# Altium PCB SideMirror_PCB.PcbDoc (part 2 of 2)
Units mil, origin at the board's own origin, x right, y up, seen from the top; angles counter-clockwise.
Board outline 2391.73 x 2364.18 mil, 2 copper layers (Top Layer, Bottom Layer), stack 62 mil thick; 77 components, 73 nets, 281 pads, 345 vias.
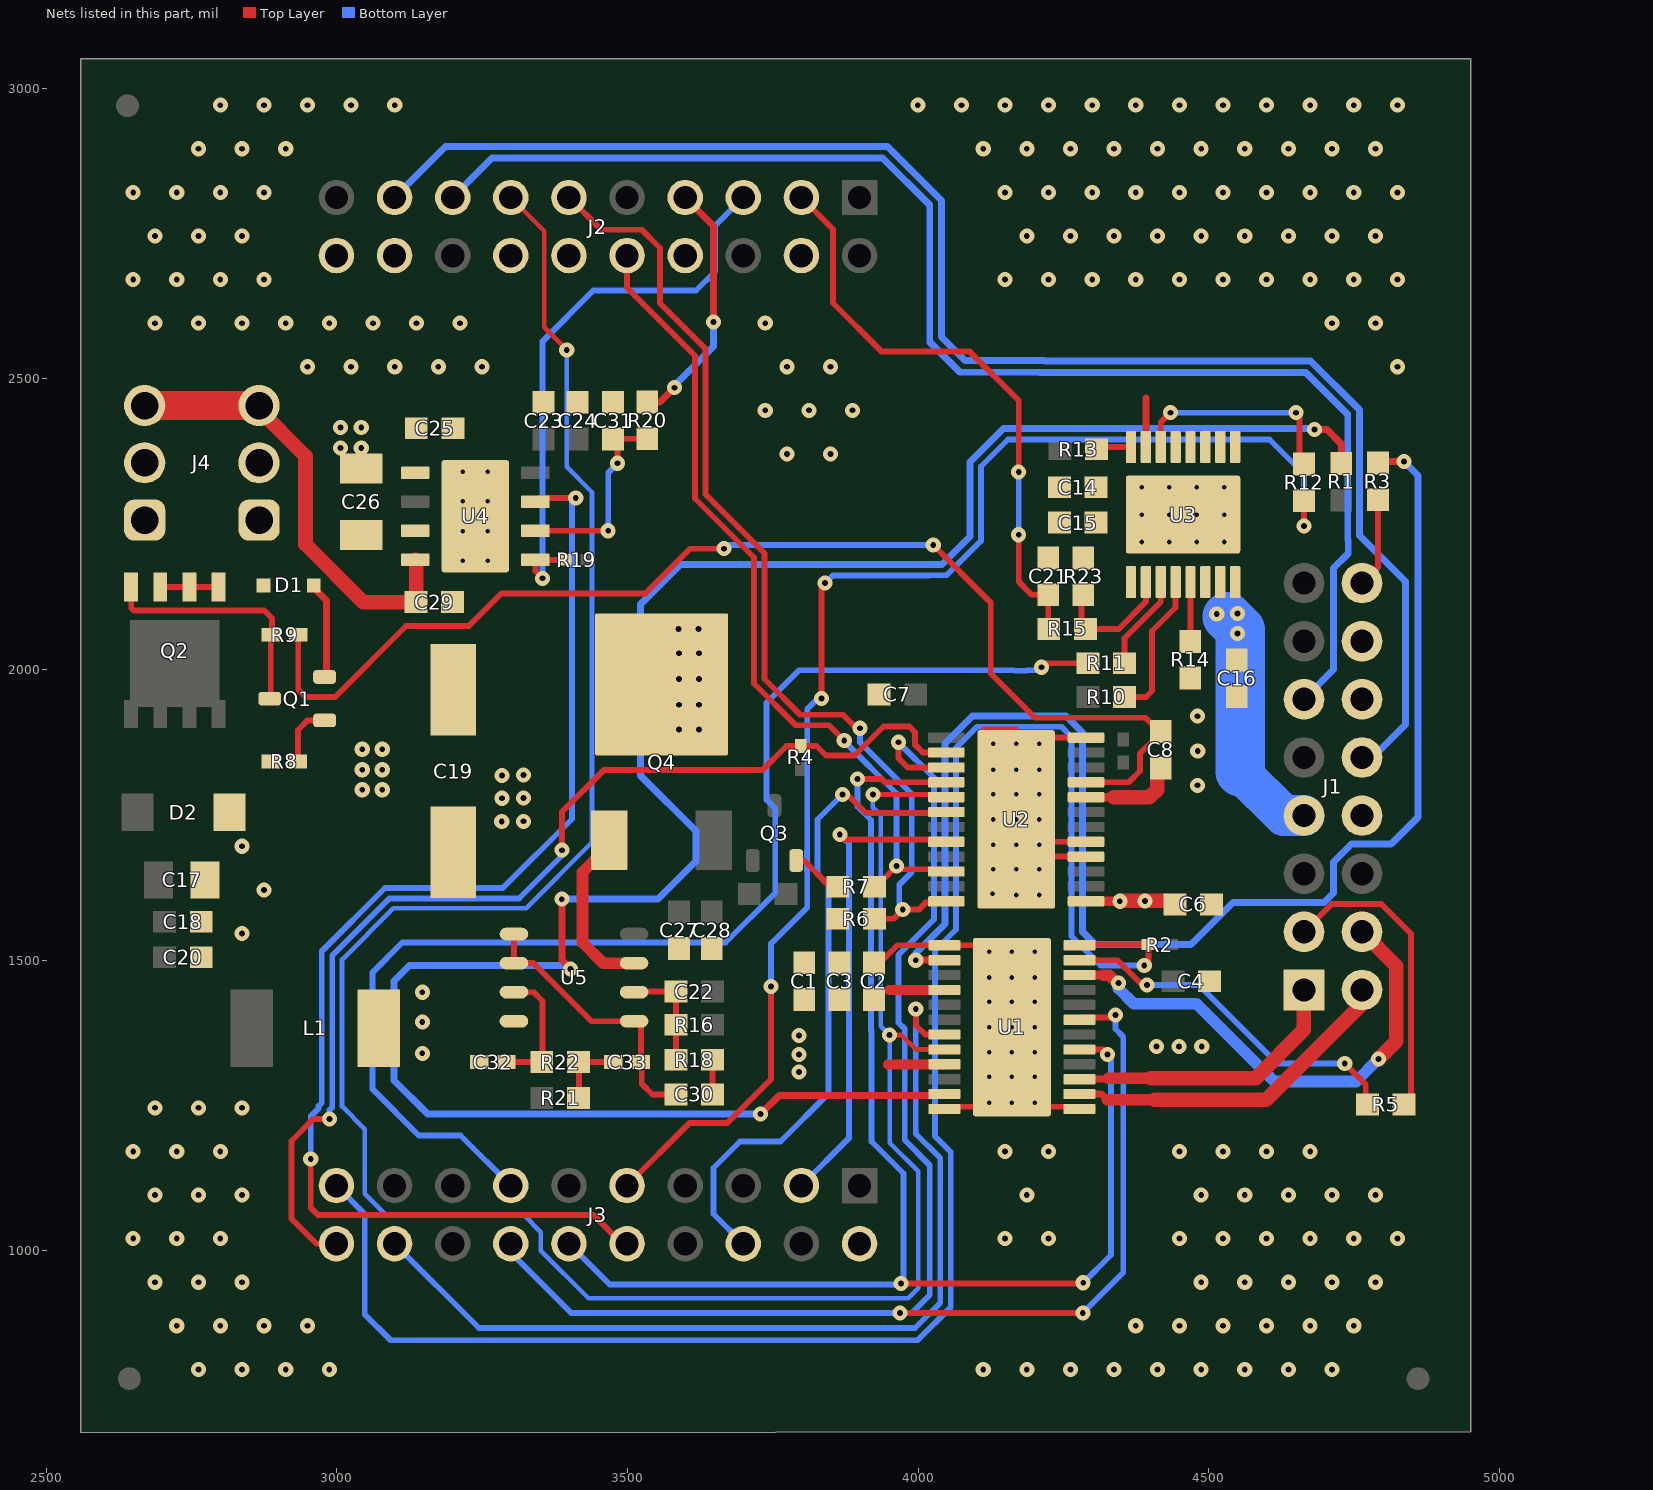
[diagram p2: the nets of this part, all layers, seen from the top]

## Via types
v1: diameter 26, hole 10, Top Layer to Bottom Layer, tented top, 270 vias
v2: diameter 19.68, hole 7.87, Top Layer to Bottom Layer, 46 vias
v3: diameter 19.68, hole 7.87, Top Layer to Bottom Layer, tented both sides, 28 vias
v4: diameter 28, hole 12, Top Layer to Bottom Layer, 1 vias

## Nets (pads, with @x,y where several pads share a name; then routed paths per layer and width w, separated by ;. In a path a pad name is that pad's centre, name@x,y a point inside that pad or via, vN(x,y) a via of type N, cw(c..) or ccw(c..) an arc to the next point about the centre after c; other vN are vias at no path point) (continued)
GND: C1.2 C2.2 C3.1 C4.2 C6.1 C7.2 C14.2 C15.2 C16.2 C17.2 C18.2 C19.2 C20.2 C21.1 C23.1 C24.1 C25.1 C26.2 C27.2 C28.2 C29.2 C31.1 C32.2 D2.2 J1.8 J1.12 J1.14 J2.4 J3.2 J4.2 Q3.2 R6.1 R7.1 R8.2 R23.1 U1.1 U1.13 U1.24 U1.25 U2.16 U2.17 U2.24 U2.25@4168.79,1742.13 U3.1 U3.9 U3.10 U3.11 U3.12 U3.13 U3.15 U4.3 U4.9@3238.19,2263.78 U5.4 | length 1580.5
  Top Layer w10: Q3.2@3790.19,1671.51 3803.61,1671.51 3848.85,1626.26 R7.1@3861.72,1626.26 ; C2.2@3924,1495.5 3934.41,1495.5 3964.5,1525.59 3985,1525.59 3985.28,1525.87 4006.72,1525.87 4007,1525.59 U1.13@4045.27,1525.59 4111.41,1525.59 4122.71,1514.29 4149.71,1514.29 4152,1512 4152,1455.71 4152,1394.26 v2(4161.42,1384.84) 4161.42,1361.22 U1.25@4161.42,1360.24 ; U1.24@4045.27,1244.09 4049.13,1247.95 4119.86,1247.95 4161.42,1289.51 4161.42,1313.98 U1.25@4161.42,1360.24 ; 4113.12,1897.13 4168.79,1897.13 v3(4168.79,1872.05) U2.25@4168.79,1831 ; U2.25@4208.16,1703.74 U2.17@4288.87,1703.74 ; U1.1@4277.56,1244.09 4273.7,1247.95 4206.05,1247.95 4203,1251 4203,1318.65 U1.25@4161.42,1360.24 ; U2.16@4288.87,1678.15 4232.77,1678.15 v2(4168.79,1742.13) v2(4168.79,1785.43) v2(4168.79,1827.56) U2.25@4168.79,1831 ; U2.24@4288.87,1882.87 4220.66,1882.87 U2.25@4168.79,1831
  Top Layer w12: U3.15@4391.82,2368.07 U3.15@4391.82,2382.83 4391.82,2467.24
  other v1: 2762,796 2837,796 2912,796 2987,796 4112,796 4187,796 4262,796 4337,796 4412,796 4487,796 4562,796 4637,796 4712,796 2724.5,871 2799.5,871 2874.5,871 2949.5,871 4374.5,871 4449.5,871 4524.5,871 4599.5,871 4674.5,871 4749.5,871 2687,946 2762,946 2837,946 4487,946 4562,946 4637,946 4712,946 4787,946 2649.5,1021 2724.5,1021 2799.5,1021 4149.5,1021 4224.5,1021 4449.5,1021 4524.5,1021 4599.5,1021 4674.5,1021 4749.5,1021 4824.5,1021 2687,1096 2762,1096 2837,1096 4187,1096 4487,1096 4562,1096 4637,1096 4712,1096 4787,1096 2649.5,1171 2724.5,1171 2799.5,1171 4149.5,1171 4224.5,1171 4449.5,1171 4524.5,1171 4599.5,1171 4674.5,1171 2687,1246 2762,1246 2837,1246 4410,1351.3 4449,1351.3 4488,1351.3 2837,1546 2874.5,1621 2837,1696 3283.7,1738.47 3321,1738.9 3284.13,1778.57 3321,1779 3284.13,1818 3321,1818.43 3774.5,2371 3849.5,2371 3737,2446 3812,2446 3887,2446 2949.5,2521 3024.5,2521 3099.5,2521 3174.5,2521 3249.5,2521 3774.5,2521 3849.5,2521 4824.5,2521 2687,2596 2762,2596 2837,2596 2912,2596 2987,2596 3062,2596 3137,2596 3212,2596 3737,2596 4712,2596 4787,2596 2649.5,2671 2724.5,2671 2799.5,2671 2874.5,2671 4149.5,2671 4224.5,2671 4299.5,2671 4374.5,2671 4449.5,2671 4524.5,2671 4599.5,2671 4674.5,2671 4749.5,2671 4824.5,2671 2687,2746 2762,2746 2837,2746 4187,2746 4262,2746 4337,2746 4412,2746 4487,2746 4562,2746 4637,2746 4712,2746 4787,2746 2649.5,2821 2724.5,2821 2799.5,2821 2874.5,2821 4149.5,2821 4224.5,2821 4299.5,2821 4374.5,2821 4449.5,2821 4524.5,2821 4599.5,2821 4674.5,2821 4749.5,2821 4824.5,2821 2762,2896 2837,2896 2912,2896 4112,2896 4187,2896 4262,2896 4337,2896 4412,2896 4487,2896 4562,2896 4637,2896 4712,2896 4787,2896 2799.5,2971 2874.5,2971 2949.5,2971 3024.5,2971 3099.5,2971 3999.5,2971 4074.5,2971 4149.5,2971 4224.5,2971 4299.5,2971 4374.5,2971 4449.5,2971 4524.5,2971 4599.5,2971 4674.5,2971 4749.5,2971 4824.5,2971
  other v2: 4122.05,1341.54 4161.42,1341.54 4200.79,1341.54 4122.05,1384.84 4200.79,1384.84 4122.05,1428.15 4161.42,1428.15 4200.79,1428.15 4129.42,1656.69 4168.79,1656.69 4208.16,1656.69 4129.42,1698.82 4168.79,1698.82 4208.16,1698.82 4129.42,1742.13 4208.16,1742.13 4129.42,1785.43 4208.16,1785.43 4129.42,1827.56 4208.16,1827.56 3216.54,2238.19 3259.84,2238.19 3216.54,2289.37 3259.84,2289.37
  other v3: 4122.05,1254.92 4161.42,1254.92 4200.79,1254.92 4122.05,1299.41 4161.42,1299.41 4200.79,1299.41 4122.05,1470.28 4161.42,1470.28 4200.79,1470.28 4122.05,1514.76 4161.42,1514.76 4200.79,1514.76 4168.79,1612.2 4208.16,1612.2 4128,1614 4129.42,1872.05 4208.16,1872.05 3216.54,2187.01 3259.84,2187.01 3216.54,2340.55 3259.84,2340.55
HALLX: J1.10 J2.17 | length 2702.8
  Bottom Layer w12: J2.17@3108,2812.2 J2.17@3099.21,2812.2 3186.88,2899.87 3947.23,2899.87 4039.87,2807.23 4039.87,2572.13 4080.58,2531.42 4216.75,2531.42 4217.3,2530.87 4675.14,2530.87 4759.04,2446.97 4759.04,2230.96 4838.59,2151.41 4838.59,1905.81 4781.6,1848.82 J1.10@4763.78,1848.82
HALLY: J1.11 J2.15 | length 2410.4
  Bottom Layer w12: J2.15@3199.21,2812.2 3267.01,2880 3939,2880 4020,2799 4020,2563.89 4072.34,2511.55 4208.52,2511.55 4209.07,2511 4666.9,2511 4739.17,2438.74 4739.17,2222.73 4740,2221.89 4740,2199.96 4714.91,2174.87 4714.91,1999.94 J1.11@4663.78,1948.82
HEATER: C16.1 J1.7 U3.6 U3.7 U3.8 | length 420
  Top Layer w12: U3.6@4491.32,2150.54 U3.6@4494.18,2150.54
  Bottom Layer w70: 4554,1824 4629.18,1748.82 J1.7@4663.78,1748.82
  Bottom Layer w85: 4531.65,2090.96 4554,2068.62 4554,1824
  other v1: 4549.69,2061.97 4513.79,2095.78 4549.69,2096.22
HEATERBTN: J2.20
IPROP1l: J2.10 R7.2 U2.10 | length 1402.4
  Top Layer w10: J2.10@3499.21,2712.2 3499.21,2656.79 3616.17,2539.83 3616.17,2294.42 3717.72,2192.87 3717.72,1976.24 3789.6,1904.37 3846.63,1904.37 v1(3873,1878) ; R7.2@3937.89,1639.44 3939.16,1638.16 v1(3963,1662) 3963,1659.32 3965.91,1656.42 4044.85,1656.42 U2.10@4048.71,1652.56
  Bottom Layer w10: v1(3873,1878) 3873,1876.72 3963,1786.72 v1(3963,1662)
IPROP2l: J2.11 R6.2 U2.12 | length 1708
  Top Layer w10: J2.11@3399.21,2812.2 3454.87,2756.54 3524.61,2756.54 3555.83,2725.33 3555.83,2630.14 3634.04,2551.92 3634.04,2301.83 3735.6,2200.27 3735.6,1983.65 3797,1922.24 3870.76,1922.24 3894,1899 v1(3900,1899) ; R6.2@3924.71,1571.26 3957.89,1571.26 v1(3973.63,1587) 4000.95,1587 4012.95,1599 4039.18,1599 4045.14,1604.95 U2.12@4048.71,1601.38
  Bottom Layer w10: v1(3900,1899) 3900,1875 3989.1,1785.9 3989.1,1651.5 3967.55,1629.96 3967.55,1593.07 v1(3973.63,1587)
L3: R5.1 U1.11 | length 624.8
  Top Layer w10: U1.11@4277.56,1500 4343.05,1500 v1@4389,1454.05 ; v1@4389.75,1453.31 v1@4389,1454.05 ; v1(4393.87,1457.13) 4392.07,1457.13 v1@4389,1454.05 ; v1(4734,1322.25) 4770,1286.25 4770,1262.5 4759.14,1251.64 R5.1@4760.25,1251.64
  Bottom Layer w10: v1(4393.87,1457.13) 4483.03,1457.13 4617.9,1322.25 v1(4734,1322.25)
LATCH: J3.13 R11.1 | length 2171.9
  Top Layer w10: v1(4212,2004) 4218.99,2010.99 R11.1@4292.06,2010.99
  Bottom Layer w10: J3.13@3299.21,1112.2 3212.87,1198.55 3141.05,1198.55 3061.5,1278.1 3061.5,1479.32 3112.42,1530.24 3668.79,1530.24 3754.25,1615.69 3754.25,1760.88 3739.25,1775.88 3739.25,1942.9 3795.12,1998.77 4165.06,1998.77 4165.74,1998.1 4187.18,1998.1 4187.85,1998.77 4206.77,1998.77 v1(4212,2004)
LBLSP: R1.1 U1.23 | length 3794
  Top Layer w12: v1(3387,1605) 3387,1500 v1(3402,1485) ; v1(3729,1235.3) 3760.53,1266.83 4042.42,1266.83 U1.23@4045.27,1269.68 ; v1(4681.98,2412.87) 4703.31,2412.87 4728,2388.18 R1.1@4728,2354.33
  Bottom Layer w12: v1(3387,1605) 3552.31,1605 3618,1670.69 3618,1722 3522,1818 3522,2112 3591,2181 4009.24,2181 4009.37,2181.13 4041.13,2181.13 4089.25,2229.25 4089.25,2282.32 4089.44,2282.51 4089.44,2357.18 4147.02,2414.75 4680.11,2414.75 v1(4681.98,2412.87) ; v1@3399.21,1482.21 v1(3402,1485) 3396,1491 3125.15,1491 3098.25,1464.1 3098.25,1293.33 3156.27,1235.3 v1(3729,1235.3)
LED: J2.18
LED3: J1.3 R5.2 | length 524.2
  Top Layer w10: J1.3@4663.78,1548.82 4711.65,1596.69 4796.92,1596.69 4848,1545.61 4848,1263.69 R5.2@4835.95,1251.64
LEFT: J2.12
LIN: C29.1 J4.3 U4.4 | length 1010.2
  Top Layer w25: J4.3@2852.65,2460.63 2859.15,2454.14 2862.65,2450.64 2946,2367.29 2946,2215.74 3045.6,2116.14 C29.1@3136.22,2116.14 3136.22,2187.4 U4.4@3134.84,2188.78
  Top Layer w50: J4.3@2669.3,2454.14 2859.15,2454.14 J4.3@2866.15,2454.14
  Bottom Layer w10: J4.3@2852.65,2460.63 2872.66,2460.63 J4.3@2872.66,2452.34
  Bottom Layer w50: J4.3@2669.3,2454.14 J4.3@2866.15,2454.14
LTURN: R3.1 U1.14 | length 2430.5
  Top Layer w12: v1(3996,1500) U1.14@4045.27,1500 ; R3.1@4791,2355.1 4793.9,2358 v1(4835.95,2358)
  Bottom Layer w12: v1(3996,1500) 3996,1512.31 4046.13,1562.43 4046.13,1873.13 4093.45,1920.45 4254.39,1920.45 4282.9,1891.94 4282.9,1548.92 4304.82,1527 4469.59,1527 4541.59,1599 4698,1599 4714.91,1615.91 4714.91,1669.06 4745.79,1699.94 4813.94,1699.94 4860,1746 4860,2333.95 v1(4835.95,2358)
NetC22_2: C22.2 R16.1 R18.2 U5.6 | length 189.8
  Top Layer w10: U5.6@3511.35,1445 3512.35,1446 C22.2@3583.5,1446 R16.1@3583.5,1389 R18.2@3583.5,1328.74
NetC30_1: C30.1 R18.1 | length 59.7
  Top Layer w10: C30.1@3646.5,1269 R18.1@3646.5,1328.74
NetC30_2: C30.2 C33.1 U5.1 U5.2 U5.5 | length 484.5
  Top Layer w10: U5.1@3304.65,1545 U5.2@3304.65,1495 3338,1495 3438,1395 U5.5@3511.35,1395 3523.03,1395 3523.03,1326.39 3524.62,1324.79 3524.62,1287.55 3543.17,1269 C30.2@3583.5,1269
NetC31_2: C31.2 R20.2 U4.6 | length 349.3
  Top Layer w10: U4.6@3341.54,2238.78 v1(3466.75,2238.78) ; v1(3483,2355) 3483,2389.24 C31.2@3475.24,2397 R20.2@3531.17,2397
  Bottom Layer w10: v1(3466.75,2238.78) 3466.75,2338.75 v1(3483,2355)
NetC32_1: C32.1 R22.2 U5.3 | length 220.2
  Top Layer w10: C32.1@3293.82,1324.79 3353.64,1324.79 3353.64,1429.98 3338.62,1445 U5.3@3304.65,1445
NetC33_2: C33.2 R21.2 R22.1 | length 122.5
  Top Layer w10: R21.2@3416.63,1263 3416.63,1324.79 C33.2@3477.38,1324.79
NetD1_2: D1.2 Q1.2 | length 169.7
  Top Layer w12: D1.2@2956.31,2145 2982.28,2119.02 2982.28,1990.71 Q1.2@2978.98,1987.4
NetQ1_1: Q1.1 R8.1 | length 106.6
  Top Layer w10: R8.1@2933.24,1842 2933.24,1896.06 2949.79,1912.6 Q1.1@2978.98,1912.6
NetQ1_3: Q1.3 Q2.4 R9.1 | length 425.8
  Top Layer w10: Q2.4@2646.1,2142.3 2646.1,2106.3 2650.71,2101.69 2874.93,2101.69 2888.62,2088 2888.62,2062.25 R9.1@2886.38,2060 2886.38,1951.89 Q1.3@2884.49,1950
NetQ4_1: Q4.1 U5.7 | length 302.7
  Top Layer w20: Q4.1@3478.15,1706.69 3422.63,1651.18 3422.63,1530.37 3458,1495 U5.7@3511.35,1495
NetR10_2: R10.2 U3.4 | length 255.6
  Top Layer w10: R10.2@4355.06,1953 4392,1953 4402.27,1963.27 4402.27,2066.27 4443,2107 U3.4@4443,2150.54
NetR11_2: R11.2 U3.3 | length 165.4
  Top Layer w10: R11.2@4355.05,2010.99 4355.05,2054.04 4417.41,2116.39 U3.3@4417.41,2150.54
NetR12_2: R12.2 U3.14 | length 382.2
  Top Layer w10: U3.14@4417.41,2382.83 4417.41,2425.41 v1(4434,2442) ; v1(4650,2442) 4656.11,2435.89 4656.11,2361.17 R12.2@4663.78,2353.5
  Bottom Layer w10: v1@4428.03,2442 v1(4434,2442) v1(4650,2442)
NetR13_2: R13.2 U3.16 | length 58.8
  Top Layer w10: R13.2@4309.53,2388 4314.7,2382.83 U3.16@4366.23,2382.83
NetR14_2: R14.2 U3.5 | length 125.1
  Top Layer w10: U3.5@4472.45,2150.54 U3.5@4468.59,2150.54 R14.2@4468.59,2049.63 ; R14.2@4468.59,2049.63 R14.2@4470.12,2048.1 ; R14.2@4468.59,2049.63 R14.2@4470.12,2048.1 ; R14.2@4470.12,2048.1 4470.12,2056.13 R14.2@4470.12,2048.1
NetR15_2: R15.2 R23.2 U3.2 | length 222.6
  Top Layer w10: R23.2@4286.07,2120.46 4281.03,2125.5 4281.03,2076.72 R15.2@4287.75,2070 4345.06,2070 4391.82,2116.76 U3.2@4391.82,2150.54
nFAULT_8873: J3.20 R4.1 U2.2 | length 1921.4
  Top Layer w10: v1(2987.1,1227) 2959.97,1227 2922,1189.03 2922,1055.21 2965,1012.2 J3.20@2999.21,1012.2 J3.20@2999.21,1026.79 ; v1(3387.5,1689.32) 3387.5,1755.5 3459,1827 3732,1827 3773.5,1868.5 R4.1@3798,1868.5 3825.04,1868.5 3841.42,1852.13 3890.44,1852.13 3940.31,1902 3984.77,1902 3994.87,1891.9 3994.87,1870.46 4008.05,1857.28 U2.2@4048.71,1857.28 U2.2@4044.85,1861.14
  Bottom Layer w10: v1(2987.1,1227) 2987.1,1242.21 2992,1247.11 2992,1508.11 3090.14,1606.24 3313.47,1606.24 3387.5,1680.28 v1(3387.5,1689.32)
nFAULT_8906: J3.19 R2.1 U1.12 | length 3148.9
  Top Layer w10: U1.12@4277.56,1525.59 4278.97,1527 R2.1@4396.31,1527 4396.31,1498.31 v1(4389,1491)
  Bottom Layer w10: J3.19@2999.21,1112.2 3048,1063.42 3048,890.53 3092.53,846 3999,846 4056,903 4056,1170 4029,1197 4029,1516.84 4065,1552.84 4065,1865.31 4101.26,1901.57 4246.58,1901.57 4264.03,1884.12 4264.03,1541.1 4314.06,1491.06 4314,1491 v1(4389,1491)
nRST: J3.10 U4.7 | length 2170.5
  Top Layer w10: v1(2955,1158) 2955,1074 2967.17,1061.83 3440.95,1061.83 3490.58,1012.2 J3.10@3499.21,1012.2 ; U4.7@3341.54,2288.78 3347.76,2295 v1(3411,2295)
  Bottom Layer w10: v1(2955,1158) 2955,1231.49 2968.6,1245.09 2968.6,1248.99 2974.13,1254.52 2974.13,1515.51 3082.74,1624.12 3285.42,1624.12 3404.36,1743.06 3404.36,2288.36 v1(3411,2295)
nSCS_8873: J3.6 U2.6 | length 1149.1
  Top Layer w10: v1@3874.12,1789.12 3870,1793.24 v1(3870,1785) 3878.24,1785 3910.12,1753.13 4046.91,1753.13 U2.6@4048.71,1754.92
  Bottom Layer w10: J3.6@3699.21,1012.2 3648,1063.42 3648,1142.55 3693.45,1188 3763.22,1188 3845.59,1270.38 3845.59,1629.52 3827,1648.11 3827,1660.04 3826.89,1660.16 3826.89,1681.59 3827,1681.71 3827,1742 v1(3870,1785)
nSCS_8906: J3.18 U1.19 | length 1629.4
  Top Layer w10: v1(3996,1416) 3996,1388.25 3997.34,1386.91 4012.2,1372.05 U1.19@4045.27,1372.05
  Bottom Layer w10: J3.18@3099.21,1012.2 3244.42,867 3994.72,867 4038,910.28 4038,1159.52 3997.34,1200.17 3996,1201.52 v1(3996,1416) 3990.42,1416 v1@3990.37,1415.94
PH_8873: J3.3 U2.8 | length 833
  Top Layer w10: v1(3865.32,1716.09) 3873.81,1707.6 4044.85,1707.6 U2.8@4048.71,1703.74
  Bottom Layer w10: J3.3@3799.21,1112.2 3881.34,1194.33 3881.34,1700.06 v1(3865.32,1716.09)
RIGHT: J2.14
RXD: J2.5 R19.1 U4.5 | length 995.1
  Top Layer w10: v1@3359.64,2157 v1(3354,2157) 3341.54,2169.46 U4.5@3341.54,2188.78 3391.42,2188.78 R19.1@3391.93,2189.29
  Bottom Layer w10: v1(3354,2157) 3354,2565 3441,2652 3618,2652 3651,2685 3651,2763.99 J2.5@3699.21,2812.2
SCLK: J2.13 U1.20 U2.5 | length 4270.3
  Top Layer w8: J2.13@3299.21,2812.2 3356.83,2754.59 3356.83,2588.7 v1(3395.53,2550) ; v1(3922.16,1785) 4034.8,1785 4037.8,1782 4040.8,1785 4046.8,1779 4047,1779.2 4047.2,1779 U2.5@4048.71,1780.51 ; v1(3951,1371.27) 3970.99,1371.27 3995.81,1346.46 U1.20@4045.27,1346.46
  Bottom Layer w8: v1(3395.53,2550) 3395.53,2348.68 3438.97,2305.24 3438.97,1702.76 3325.58,1589.37 3097.13,1589.37 3008.88,1501.12 3008.88,1248.37 3048,1209.25 3048,1098.16 3084.33,1061.83 3321.17,1061.83 3351,1032 3351,1000.48 3432.85,918.63 3982.83,918.63 3999.95,935.75 3999.95,1136.55 3951,1185.5 v1(3951,1371.27) 3936,1386.27 3936,1749 3922.16,1762.84 v1(3922.16,1785)
SDI: J3.12 U1.5 U2.4 | length 2453
  Top Layer w10: v1(3895.92,1812) 3936.87,1812 3942.77,1806.1 U2.4@4048.71,1806.1 ; v1@3972,942 v1(3970.5,943.5) v1@3973.35,943.5 ; v1@3972,948.15 3975,945.15 v1@3973.35,943.5 ; U1.5@4277.56,1346.46 4317.53,1346.46 v1(4326,1337.99) ; v1(4284,945) 4282.5,943.5 v1@3973.35,943.5
  Bottom Layer w10: J3.12@3399.21,1012.2 3469.42,942 3975,942 3975,1132.87 3919.71,1188.16 3919.71,1378.7 3919.13,1379.28 3919.13,1741.38 3895.92,1764.59 v1(3895.92,1812) ; v1(4284,945) 4332,993 4332,1331.99 v1(4326,1337.99)
SDO: J3.14 U1.7 U2.3 | length 2863.4
  Top Layer w10: v1(3969,893) v1(4283.39,893) ; v1@3969,1878 v1(3966,1875) 3966,1848 3982.31,1831.69 U2.3@4048.71,1831.69 ; U1.7@4277.56,1397.64 4281.42,1401.5 4335.16,1401.5 v1(4339.41,1405.75)
  Bottom Layer w10: J3.14@3299.21,1012.2 3299.21,997.16 3403.37,893 v1(3969,893) 3989.1,893 4020,923.91 4020,1147.39 3976.87,1190.51 3976.87,1381.99 3966,1392.87 3966,1509 3995.4,1538.4 4027.25,1570.25 4027.25,1813.75 v1(3966,1875) ; v1(4283.39,893) 4352.91,962.52 4352.91,1368.09 4339.41,1381.59 v1(4339.41,1405.75)
SEL1: J3.9 R12.1 | length 2386.3
  Top Layer w10: J3.9@3499.21,1112.2 3607.17,1220.16 3671.9,1220.16 3747,1295.26 v1(3747,1455) ; v1(3834,1950) 3834,2142.82 v1(3840,2148.82) ; v1(4663.78,2247) R12.1@4663.78,2290.5
  Bottom Layer w10: v1(3747,1455) 3747,1528.47 3809.13,1590.6 3809.13,1652.64 3809.01,1652.75 3809.01,1689 3809.13,1689.11 3809.13,1932.23 3832.9,1956 3834,1954.9 v1(3834,1950) ; v1(3840,2148.82) 3853.05,2161.87 4018.87,2161.87 4019.25,2162.25 4048.94,2162.25 4108.13,2221.43 4108.13,2274.5 4108.32,2274.69 4108.32,2349.36 4154.83,2395.87 4604.44,2395.87 4663.78,2336.53 v1(4663.78,2247)
SNS: C21.2 J2.3 R15.1 | length 1026.6
  Top Layer w10: J2.3@3799.21,2812.2 3853.7,2757.72 3853.7,2630.8 3937.5,2547 4089,2547 4173,2463 v1(4173,2340) ; v1(4173,2232) 4173,2151 4195.25,2128.75 C21.2@4224.03,2128.75 4224.03,2070.73 R15.1@4224.76,2070
  Bottom Layer w10: v1(4173,2232) 4173,2334 4170,2337 v1(4173,2340)
TURN: J1.16 R3.2 | length 154.6
  Top Layer w10: J1.16@4763.78,2148.82 4791,2176.04 R3.2@4791,2292.11
TXD: J2.7 R20.1 | length 437.7
  Top Layer w12: R20.1@3531.17,2459.99 3555.94,2459.99 v1(3580.95,2485) ; J2.7@3599.21,2812.2 3648,2763.42 v1(3648,2598)
  Bottom Layer w12: v1@3576.55,2484.45 3648,2555.89 v1(3648,2598)
UP: J2.8
Vbat: D1.1 J4.1 Q2.1 Q2.2 Q2.3 | length 102.3
  Top Layer w10: Q2.3@2694.49,2143.91 Q2.3@2696.1,2142.3 Q2.2@2746.1,2142.3 Q2.1@2796.1,2142.3
VCP: C8.2 R9.2 U2.21 | length 2073.8
  Top Layer w10: R9.2@2931.73,2064.29 R9.2@2932.8,2063.23 ; R9.2@2933.62,2060 2933.62,1965.38 2946,1953 2997,1953 3119,2075 3227,2075 3283.13,2131.13 3530.83,2131.13 3607.7,2208 v1(3666,2208) ; v1(4026,2214.36) 4118.29,2122.07 4125,2115.33 4125,1993.23 4201.23,1917 4391.26,1917 4410,1898.26 4410,1884 4381.88,1855.88 4381.88,1825.45 4362.53,1806.1 U2.21@4288.87,1806.1
  Bottom Layer w10: v1(3666,2208) 3672.36,2214.36 v1(4026,2214.36)
Vsup: C1.1 C2.1 C3.2 C6.2 C8.1 C14.1 C15.1 C19.1 C25.2 C26.1 L1.2 Q4.4 R14.1 U1.16 U1.21 U2.13 U2.20 U3.17@4455.8,2266.69 U4.1 | length 685.3
  Top Layer w10: L1.2@3066.57,1358.27 L1.2@3066.57,1393.35
  Top Layer w12: U2.13@4288.87,1599.83 U2.13@4288.87,1601.38 ; R14.1@4468.03,1983.7 R14.1@4468.03,1985.5
  Top Layer w15: U2.20@4288.87,1780.51 4336.5,1780.51
  Top Layer w17: 3947.69,1320.87 U1.21@4045.27,1320.87 ; 3949.73,1448.82 U1.16@4045.27,1448.82 ; U2.13@4317,1601.38 v1(4347,1601.38)
  Top Layer w25: Q4.4@3475.04,1974.41 Q4.4@3558.63,1974.41 Q4.4@3567.91,1974.41 ; 4336.5,1780.51 4398,1780.51 4411.1,1793.61 4411.1,1810.27 ; v1(4347,1601.38) 4347.62,1602 v1(4390.14,1602) 4429.51,1602 C6.2@4430.12,1601.38 ; U3.17@4404.2,2318.28 U3.17@4455.8,2266.69 ; C6.2@4441.5,1590 C6.2@4430.12,1601.38 ; C6.2@4441.69,1596 4436.31,1601.38 C6.2@4430.12,1601.38
  other v1: 3794.87,1307.48 3795,1338 3147,1339.79 3794.87,1370.3 3147,1393.79 3147,1444.79 3043.62,1793.24 3078.11,1793.24 4480.71,1800.85 3043.62,1827.56 3078.11,1827.56 4481.07,1860 3043.62,1863 3078,1863 3588.61,1897.13 3623.1,1897.13 4480.71,1919.85 3588.61,1939.63 3623.1,1939.63 3588.72,1983.65 3623.1,1983.65 3588.61,2028 3623.1,2028 3587.79,2070 3622.17,2070 3006,2381.3 3042,2381.3 3006,2416.58 3042,2416.58
  other v2: 4432.17,2219.44 4479.42,2219.44 4432.17,2266.69 4479.42,2266.69 4432.17,2313.93 4479.42,2313.93
  other v3: 4384.93,2219.44 4526.66,2219.44 4384.93,2266.69 4526.66,2266.69 4384.93,2313.93 4526.66,2313.93
X1: J1.1 U1.3 | length 497.9
  Top Layer w12: U1.3@4277.56,1295.28 4323.38,1295.27
  Top Layer w20: 4327.26,1297.06 4400.6,1297.06
  Top Layer w25: 4400.6,1297.06 4580.67,1297.06 4663.78,1380.17 J1.1@4663.78,1448.82 J1.1@4654.96,1440
X2/Y1: J1.4 U1.10 | length 867.8
  Top Layer w15: U1.10@4277.56,1474.41 4318.42,1474.41
  Top Layer w20: 4318.42,1474.41 4328.88,1474.41 4342.28,1461 v1(4344.72,1461)
  Top Layer w25: J1.4@4763.78,1548.82 4822.63,1489.97 4822.63,1360.63 v1(4791.93,1329.93)
  Bottom Layer w20: v1(4344.72,1461) 4344.72,1451.37 4371.1,1425 4479,1425 4612.62,1291.38 4753.38,1291.38 v1(4791.93,1329.93)
Y2: J1.2 U1.2 | length 582.5
  Top Layer w12: U1.2@4277.56,1269.68 4315.75,1269.68 4325.43,1260
  Top Layer w20: 4325.43,1260 4407,1260
  Top Layer w25: 4407,1260 4599,1260 4763.78,1424.78 J1.2@4763.78,1448.82
pads on no net: FID1.1 FID2.1 FID3.1 J1.9 J2.19 J3.8 J3.16 U1.4 U1.9 U1.15 U1.17 U1.18 U1.22 U2.25@4168.79,1742.13 U3.17@4455.8,2266.69 U4.9@3238.19,2263.78

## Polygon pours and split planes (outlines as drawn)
Vbat on Top Layer "TOP_LAYER_VBAT_P038" (solid, remove dead copper, pour order 38): 2905,2298.48 2905,2127.75 2674.64,2127.75 2592.49,2209.9 2592.49,2278.79 2612.17,2298.48
no net on Top Layer "TOP_LAYER_NONET_P040" (solid, remove dead copper, pour order 40): 2779.42,1549.85
12V on Top Layer "TOP_LAYER_12V_P036" (solid, remove dead copper, pour order 36): 2889,1317 2889,1449 2732.87,1449 2732.95,2085 2559.05,2085 2559.06,1441.19 2559.05,1317
no net on Top Layer "TOP_LAYER_NONET_P046" (solid, remove dead copper, pour order 46): 3257.87,1896.97
Vsup on Top Layer "TOP_LAYER_VSUP_P008" (solid, remove dead copper, pour order 8): 2978.98,1296 3161.33,1296 3194.57,1335.86 3194.57,1466.64 3140.03,1521.18 3140.03,1852.13 3699,1852.13 3699,2109 2978.98,2109
Vsup on Top Layer "TOP_LAYER_VSUP_P050" (solid, remove dead copper, pour order 50): 2985,2440.94 3165,2440.94 3165,2316 2985,2316
no net on Top Layer "TOP_LAYER_NONET_P064" (solid, remove dead copper, pour order 64): 4319.29,1656.69
3.3V on Top Layer "TOP_LAYER_3.3V_P082" (solid, remove dead copper, pour order 82): 3317.84,2427 3438,2427 3438,2326.26 3317.84,2326.26
no net on Top Layer "TOP_LAYER_NONET_P086" (solid, remove dead copper, pour order 86): 3415,2357.72
HEATER on Top Layer "TOP_LAYER_HEATER_P020" (solid, remove dead copper, pour order 20): 4485,2180.07 4573.03,2180.07 4573.03,1995.99 4485,1995.99
Vsup on Top Layer "TOP_LAYER_VSUP_P034" (solid, remove dead copper, pour order 34): 3763.03,1281 3960.21,1281 3960.21,1328.74 3960.21,1458.03 3759.75,1458.03
EC on Top Layer "TOP_LAYER_EC_P088" (solid, remove dead copper, pour order 88): 3568.02,1806.34 3807,1806.34 3807,1738.9 3685.53,1738.9 3685.53,1649 3610.57,1649 3567.82,1691.75
Vsup on Top Layer "TOP_LAYER_VSUP_P106" (solid, remove dead copper, pour order 106): 4284,2333.54 4389.75,2333.54 4389.75,2235 4284,2235
no net on Top Layer "TOP_LAYER_NONET_P108" (solid, remove dead copper, pour order 108): 4308.03,2214.3
no net on Top Layer "TOP_LAYER_NONET_P110" (solid, remove dead copper, pour order 110): 4337.59,2287.28
Vsup on Top Layer "TOP_LAYER_VSUP_P112" (solid, remove dead copper, pour order 112): 4390.27,1965.24 4432.03,2007 4495.47,2007 4495.47,1767.72 4273.5,1767.72 4273.5,1810.33 4390.27,1927.1
GND on Top Layer "TOP_LAYER_GND_P114" (solid, remove dead copper, pour order 114): 4949.99,704.91 4950.79,688.98 2559.06,688.98 2579.99,3035.91 4950.79,3051.18
3.3V on Top Layer "TOP_LAYER_3.3V_P032" (solid, remove dead copper, pour order 32): 3802.01,1650.83 3802.01,1555.69 3486,1555.59 3486,1650.83
3.3V on Top Layer "TOP_LAYER_3.3V_P128" (solid, remove dead copper, pour order 128): 3458,1641.74 3456,1639.74 3456,1530 3563.18,1530 3568.88,1535.7 3568.88,1650.83 3454.15,1650.83 3456,1648.98 3456,1635
Vsup on Bottom Layer "BOTTOM_LAYER_VSUP_P078" (solid, remove dead copper, pour order 78): 3820.9,1435.47 3820.9,1266 3148.67,1266 3099.21,1315.46 3099.21,1469.04 3787.33,1469.04
no net on Bottom Layer "BOTTOM_LAYER_NONET_P080" (solid, remove dead copper, pour order 80): 3145,1435
no net on Bottom Layer "BOTTOM_LAYER_NONET_P092" (solid, remove dead copper, pour order 92): 3145,1435
no net on Bottom Layer "BOTTOM_LAYER_NONET_P094" (solid, remove dead copper, pour order 94): 3635,2005
no net on Bottom Layer "BOTTOM_LAYER_NONET_P098" (solid, remove dead copper, pour order 98): 3635,2005
Vsup on Bottom Layer "BOTTOM_LAYER_VSUP_P100" (solid, remove dead copper, pour order 100): 2982.28,2440.94 2983.11,2440.12 3120.41,2440.12 3120.41,1742.13 2982.28,1742.13
no net on Bottom Layer "BOTTOM_LAYER_NONET_P104" (solid, remove dead copper, pour order 104): 4128,2313
Vsup on Bottom Layer "BOTTOM_LAYER_VSUP_P076" (solid, remove dead copper, pour order 76): 3528,1812 4269,1812 4269,1581 4530,1581 4530,2092.77 4599,2198.54 4599,2361.1 4260.47,2360.87 4066.28,2166.67 3623.78,2166.67 3528,2082.18
GND on Bottom Layer "BOTTOM_LAYER_GND_P116" (solid, remove dead copper, pour order 116): 2513.45,3034.98 2516.45,3037.98 4883.45,3037.98 4883.45,703.99 2504.45,703.99

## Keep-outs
Top Layer:
  region: 4374,1689.32
Keep-Out Layer:
  text ".Layer_Name" at 577,-858.49 h60

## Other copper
Top Layer:
  rectangle net 12V: 2584.54,1879.68 2812,2085
  rectangle net FM1: 4259.84,1722.44 4319.29,1761.81
  rectangle net FM2: 4259.84,1624.02 4319.29,1656.69
  pour cut-out: 4320.03,1713.63 4329.76,1713.63 4339.86,1703.52 4340.25,1672.82 4331.63,1664.2 4320.03,1664.2
  pour cut-out: 4368,1696.83
  pour cut-out: 4234.78,1583.19 4310.45,1583.19 4310.45,1543.62 4311.76,1542.32 4310.43,1541 4234.78,1541
  pour cut-out: 4264.03,1566
  pour cut-out: 2817.85,1929.85 2817.85,1865.55 2909.6,1865.55 2912.85,1868.81 2912,1869.66 2912,1933.58 2821.58,1933.58
  pour cut-out: 4630.95,2255.82 4681.98,2255.82 4699.04,2185.04 4695,2181 4689.8,2186.2 4630.95,2186.2
  text ".Layer_Name" at 577,-858.49 h60
Bottom Layer:
  text ".Layer_Name" at 577,-858.49 h60

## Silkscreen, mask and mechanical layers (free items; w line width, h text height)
Top Overlay:
  lines w11.81: 2589,1212.88 2589,2562 ; 4923,1210.63 4925.3,2559
  lines w13.39: 2589,1212.88 4923,1210.63 ; 2589,2562 4919.3,2559
  text "'.PRJ_Number'.PCB_Rev" at 3225,789 h108.27
  text ".Layer_Name" at 577,-858.49 h60
Bottom Overlay:
  text ".Layer_Name" at 577,-858.49 h60
Top Paste:
  text ".Layer_Name" at 577,-858.49 h60
Bottom Paste:
  text ".Layer_Name" at 577,-858.49 h60
Top Solder:
  text ".Layer_Name" at 577,-858.49 h60
  text ".Layer_Name" at 577,-858.49 h60
Bottom Solder:
  text ".Layer_Name" at 577,-858.49 h60
Drill Guide:
  text ".Layer_Name" at 577,-858.49 h60
M1 Board Outline:
  the board outline again, w10
  text ".Layer_Name" at 577,-858.49 h60
M2 Board Dimensions:
  rectangle: 125,-400 500,-275
  rectangle: 0,-275 125,-150
  lines w7: 0,-275 1000,-275 ; 125,-400 125,-150 ; 250,-400 250,-150 ; 500,-400 500,-150 ; 750,-400 750,-150 ; 0,-400 0,-150 1000,-150 1000,-400 0,-400
  text ".Layer_Name" at 577,-858.49 h60
M3 3D STEP Top:
  text ".Layer_Name" at 577,-858.49 h60
M4 3D STEP Bottom:
  text ".Layer_Name" at 577,-858.49 h60
M5 Assembly Top:
  lines w10: -292,-930.17 6308,-930.17 ; -292,-726.83 6310,-726.83 ; -292,-523.5 -292,-1133.5 3713,-1133.5 6310,-1133.5 6310,-523.5 -291.5,-523.5 -291.5,-1133.5 1284,-1133.5 ; 2173,-1133.5 2173,-523.5 ; 3440,-726.83 3440,-523.5 ; 4280,-726.83 4280,-523.5 ; 4902,-1140 4902,-937.17
  text "COMPONENTS MARKED 'DNP' SHOULD NOT BE POPULATED." at 1153.5,-318.5 h60
  text "ASSEMBLY VARIANT:" at 1153,-434 h60
  text ".VariantName" at 2189,-434 h60
  text "PCB VIEWED FROM TOP SIDE" at -228.5,-655.67 h60
  text "BOARD #:" at 2248,-655.67 h60
  text ".PRJ_Number" at 2793.5,-655.67 h60
  text "REV:" at 3638,-655.67 h60
  text ".PCB_Rev" at 3929.5,-655.67 h60
  text "SVN REV:" at 4476,-655.67 h60
  text ".VersionControl_RevNumber" at 4982,-655.67 h60
  text "TID #:" at 2248,-859 h60
  text ".TID" at 2793.5,-859 h60
  text "PLOT NAME =" at -228.5,-1064.34 h60
  text ".plot_File_Name" at 577,-1064.34 h60
  text "GENERATED    :" at 2250,-1064.34 h60
  text ".Print_Date" at 3119.5,-1064.34 h60
  text ".Print_Time" at 3848.5,-1064.34 h60
  text "TEXAS INSTRUMENTS" at 5113,-1064.34 h60
M6 Assembly Bottom:
  lines w10: -292.5,-727.33 6309.5,-727.33 ; -290.5,-930.67 6309.5,-930.67 ; 1115.5,-1140.5 1115.5,-937.67 ; 1737.5,-727.33 1737.5,-524 ; 2577.5,-727.33 2577.5,-524 ; 3844.5,-1134 3844.5,-524 ; 4733.5,-1134 6309,-1134 6309,-524 -292.5,-524 -292.5,-1134 2304.5,-1134 6309.5,-1134 6309.5,-524
  text "COMPONENTS MARKED 'DNP' SHOULD NOT BE POPULATED." at 6102,-318 h60
  text ".VariantName" at 5058,-434 h60
  text "ASSEMBLY VARIANT:" at 6097,-434 h60
  text ".VersionControl_RevNumber" at 1035.5,-656.17 h60
  text "SVN REV:" at 1541.5,-656.17 h60
  text ".PCB_Rev" at 2088,-656.17 h60
  text "REV:" at 2379.5,-656.17 h60
  text ".PRJ_Number" at 3224,-656.17 h60
  text "BOARD #:" at 3769.5,-656.17 h60
  text "PCB VIEWED FROM BOTTOM SIDE" at 6246,-656.17 h60
  text ".TID" at 3224,-859.5 h60
  text "TID #:" at 3769.5,-859.5 h60
  text "TEXAS INSTRUMENTS" at 904.5,-1064.84 h60
  text ".Print_Time" at 2169,-1064.84 h60
  text ".Print_Date" at 2898,-1064.84 h60
  text "GENERATED    :" at 3767.5,-1064.84 h60
  text ".plot_File_Name" at 5440.5,-1064.84 h60
  text "PLOT NAME =" at 6246,-1064.84 h60
M9 Title Sheet:
  drawing of 57 lines, arcs and shapes, not listed
  text "1" at 739.84,8036.5 h70
  text "2" at 3235.5,8036.5 h70
  text "3" at 5724.84,8036.5 h70
  text "4" at 8231.51,8036.5 h70
  text "5" at 10730.5,8036.5 h70
  text "6" at 13235.5,8036.5 h70
  text "A" at -416.5,6893.5 h70
  text "A" at 14383.5,6893.5 h70
  text "B" at -416.5,4513.5 h70
  text "B" at 14383.5,4513.5 h70
  text "C" at -416.5,2138.5 h70
  text "C" at 14383.5,2138.5 h70
  text "PROJECT TITLE:" at 11343.5,277.5 h45
  text ".PRJ_Title" at 11393.5,144.17 h70
  text "DESIGNED FOR:" at 11343.5,-23.5 h45
  text ".PRJ_Customer" at 11393.5,-163.5 h70
  text "D" at -416.5,-231.5 h70
  text "D" at 14383.5,-231.5 h70
  text "FILE NAME:" at 11343.5,-323.5 h45
  text ".PCB_File_Name_No_Path" at 11393.5,-443.5 h70
  text "Texas Instruments (TI) and/or its licensors do not warrant the accuracy or completeness of this specification" at 6374,-605.34 h45
  text "ENGINEER:" at 11343.5,-613.5 h45
  text "LAYOUT BY:" at 12848.5,-613.5 h45
  text "or any information contained therein. TI and/or its licensors do not warrant that this design will meet" at 6329.01,-718 h45
  text ".PRJ_Engineer" at 11393.5,-768.49 h70
  text ".PCB_Layout" at 12899,-768.49 h70
  text "the specifications, will be suitable for your application or fit for any particular purpose, or will operate in" at 6329.01,-830.67 h45
  text ".Layer_Name" at 577,-858.49 h60
  text "ALTIUM DESIGNER VERSION:" at 12848.5,-923.5 h45
  text "an implementation. TI and/or its licensors do not warrant that the design is production worthy. You should" at 6329.01,-943.33 h45
  text "completely validate and test your design implementation to confirm the system functionality for your application." at 6374,-1056 h45
  text ".print_Scale" at 11393.5,-1056.83 h70
  text ".Application_BuildNumber" at 12899,-1056.83 h70
  text "1" at 739.84,-1263.5 h70
  text "2" at 3235.5,-1263.5 h70
  text "3" at 5724.84,-1263.5 h70
  text "4" at 8231.51,-1263.5 h70
  text "5" at 10730.5,-1263.5 h70
  text "6" at 13235.5,-1263.5 h70
M10 Fab Notes:
  drawing of 189 lines, arcs and shapes, not listed
  text "DESIGN INFORMATION" at 12382.02,6356.17 h60
  text "MIN. TRACK WIDTH:" at 11737.46,6224.05 h60
  text "8" at 12833.7,6224.05 h60
  text "MIL" at 12988.46,6224.05 h60
  text "MIN. CLEARANCE:" at 11737.46,6099.92 h60
  text "0.2" at 12773.7,6099.93 h60
  text "mm" at 12988.46,6099.92 h60
  text "MIN. VIA PAD SIZE:" at 11737.46,5975.8 h60
  text "24" at 12803.71,5975.8 h60
  text "MIL" at 12988.46,5975.8 h60
  text "0.05mm (2MIL)" at 12432.46,5845.9 h60
  text "MINIMUM ANNULAR RING" at 11408.23,5837.67 h60
  text "EXTERNAL" at 13140.46,5837.67 h60
  text "PER" at 11608.23,5727.55 h60
  text "IPC-D-275 CLASS 2 LEVEL C" at 11828.23,5727.54 h60
  text "MIL, HOLES" at 13316.46,5627.07 h60
  text "+/-" at 12924,5618.48 h60
  text "+/-" at 13778,5618.48 h60
  text "REGISTRATION TOLERANCES:" at 11408.23,5617.42 h60
  text "METAL" at 12608,5617.42 h60
  text "5" at 13184.2,5617.42 h60
  text "3" at 14017.2,5617.42 h60
  text "MIL" at 14133.46,5617.42 h60
  text "HOLE SIZE TOLERANCE (UNLESS OTHERWISE SPECIFIED):" at 11408.23,5519.1 h60
  text "+/-" at 13778,5516.23 h60
  text "3" at 14017.2,5515.17 h60
  text "MIL" at 14133.46,5515.17 h60
  text "MATERIAL:" at 11333.46,5377.52 h60
  text "FR-4 High Tg" at 12319.9,5249 h60
  text "X" at 12175.46,5241.01 h60
  text "FR-408" at 11754.46,5236.49 h60
  text "OTHER" at 13242.46,5236.49 h60
  text "62 MIL (1.6mm) +/-10%" at 12074.56,5093.46 h60
  text "X" at 11954.46,5091.01 h60
  text "THICKNESS:" at 11408.23,5085.24 h60
  text "OTHER" at 13359.46,5085.24 h60
  text "TOLERANCE:" at 11408.23,4946.92 h60
  text "X" at 12256.46,4946.92 h60
  text "ANSI IPC-6012 TYPE 3 CLASS 2" at 12434.48,4946.92 h60
  text "OTHER +/-" at 12434.46,4802.73 h60
  text "BOW & TWIST:" at 11408.23,4657.54 h60
  text "X" at 12256.46,4657.54 h60
  text "ANSI IPC-6012 TYPE 3 CLASS 2" at 12434.48,4657.54 h60
  text "OTHER +/-" at 12434.46,4510.85 h60
  text "DRILLING:" at 11333.46,4380.23 h60
  text "NC_DRILL FILES" at 13094.46,4275.04 h60
  text "REFERENCE:" at 11408.23,4271.1 h60
  text "X" at 12065.46,4271.01 h60
  text "AS SHOWN" at 12243.46,4271.1 h60
  text "X" at 12966.46,4271.1 h60
  text "OTHER" at 13392.46,4128.85 h60
  text "PTH COPPER THICKNESS:" at 11407.91,4125.32 h60
  text "X" at 12547.14,4125.32 h60
  text "20-30 um" at 12675.14,4125.32 h60
  text "BOARD FINISH:" at 11333.46,3977.73 h60
  text "SILKSCREEN:" at 11488.68,3867.6 h60
  text "X" at 12446.46,3867.6 h60
  text "TOP" at 12563.46,3867.6 h60
  text "X" at 12956.46,3867.6 h60
  text "BOTTOM" at 13074.46,3867.6 h60
  text "SILKSCREEN COLOR:" at 11488.68,3712.41 h60
  text "X" at 12445.46,3712.41 h60
  text "WHITE" at 12563.46,3712.41 h60
  text "OTHER" at 13074.46,3712.41 h60
  text "X" at 12576.46,3568.96 h60
  text "GREEN" at 12694.46,3568.96 h60
  text "OTHER" at 13312.46,3568.96 h60
  text "SOLDER RESIST COLOR:" at 11488.68,3562.1 h60
  text "X" at 12576.46,3414.71 h60
  text "MATTE" at 12694.46,3414.71 h60
  text "SEMI-GLOSS" at 13312,3414.07 h60
  text "IMMERSION GOLD (ENIG)" at 12394.46,3241.94 h60
  text "ENEPIG" at 13732,3234.72 h60
  text "SURFACE FINISH:" at 11333.46,3233.72 h60
  text "X" at 12216.46,3233.72 h60
  text "IMM. TIN/SILVER OR EQUIV" at 11663,3096.4 h60
  text "OTHER" at 13094.46,3092.47 h60
  text "ARRAY/PANEL:" at 11333.46,2937.09 h60
  text "CUT AND TRIM PER M1 BOARD OUTLINE" at 12394.46,2928.87 h60
  text "N.C. ROUTE" at 12394.46,2792.9 h60
  text "X" at 13082.46,2792.9 h60
  text "V. SCORE" at 13260.46,2792.9 h60
  text "CERTIFICATION:" at 11333.46,2663.77 h60
  text "MATERIALS AND WORKMANSHIP FOR ALL PCBS" at 12058.46,2663.77 h60
  text "TO MEET OR EXCEED THE REQUIREMENTS OF:" at 12058.46,2569.71 h60
  text "X" at 11695.97,2441.08 h60
  text "ANSI IPC-A-600F CLASS ->" at 11823.96,2441.08 h60
  text "X" at 13471.97,2441.08 h60
  text "2" at 13581.96,2441.08 h60
  text "1" at 13266.96,2439.58 h60
  text "3" at 13935.96,2439.58 h60
  text "X" at 12507.97,2293.39 h60
  text "RoHS" at 12635.96,2293.39 h60
  text "OTHER" at 13280.36,2293.39 h60
  text "PER ORDER" at 13677.42,2293.39 h60
  text "ALL BOARDS MUST MEET OR EXCEED UL94-V0 REQUIREMENTS." at 11361,2139.57 h60
  text "PCB MUST BEAR THE UL94V-0 UL REGISTERED MATERIAL ID NUMBER" at 11361,2023.5 h60
  text "ADDITIONAL REQUIREMENTS:" at 11333.46,1854.08 h60
  text "MICROSECTION:" at 11408.23,1746.95 h60
  text "YES" at 12313.96,1746.95 h60
  text "REQUIRED" at 13175.46,1602.62 h60
  text "BARE BOARD ELEC. TEST:" at 11408.23,1599.76 h60
  text "NONE" at 12713.96,1599.76 h60
  text "X" at 13057.46,1599.76 h60
  text "PER ORDER" at 13767.46,1599.76 h60
  text "XX MIL VIAS REQUIRE NON-CONDUCTIVE FILL AND PLANARIZE" at 11576.38,1394.82 h59
  text "XX MIL VIAS REQUIRE CONDUCTIVE FILL AND PLANARIZE" at 11584.38,1290.84 h60
  text "OUTER XX MIL TRACES REQUIRE 50 OHM SINGLE-ENDED IMPEDANCE" at 11583.39,1127.46 h58
  text "LAYER 2 & 3 (INNER LAYERS) XX MIL WIDE, XX MIL SPACE / TRACES REQUIRE 100 OHM DIFFERENTIAL IMPEDANCE" at 11575.39,891.74 h60
  text ".Layer_Name" at 577,-858.49 h60
M11 Gerber Information:
  lines w10: -292,-930.17 6308,-930.17 ; -292,-726.83 6310,-726.83 ; -292,-523.5 -292,-1133.5 3713,-1133.5 6310,-1133.5 6310,-523.5 -291.5,-523.5 -291.5,-1133.5 1284,-1133.5 ; 2173,-1133.5 2173,-523.5 ; 3440,-726.83 3440,-523.5 ; 4280,-726.83 4280,-523.5 ; 4902,-1140 4902,-937.17
  text "ALL ARTWORK VIEWED FROM TOP SIDE" at -228.5,-655.67 h60
  text "BOARD #:" at 2248,-655.67 h60
  text ".PRJ_Number" at 2793.5,-655.67 h60
  text "REV:" at 3638,-655.67 h60
  text ".PCB_Rev" at 3929.5,-655.67 h60
  text "SVN REV:" at 4476,-655.67 h60
  text ".VersionControl_RevNumber" at 4982,-655.67 h60
  text "LAYER NAME =" at -228.5,-858.49 h60
  text "TID #:" at 2248,-859 h60
  text ".TID" at 2793.5,-859 h60
  text "PLOT NAME =" at -228.5,-1064.34 h60
  text ".plot_File_Name" at 577,-1064.34 h60
  text "GENERATED    :" at 2250,-1064.34 h60
  text ".Print_Date" at 3119.5,-1064.34 h60
  text ".Print_Time" at 3848.5,-1064.34 h60
  text "TEXAS INSTRUMENTS" at 5113,-1064.34 h60
M12 Stackup:
  drawing of 191 lines, arcs and shapes, not listed
  text "Layer" at 9811.59,7402.44 h60
  text "Name" at 10221.51,7402.44 h60
  text "Material" at 11151.25,7402.44 h60
  text "Thickness" at 12011.02,7402.44 h60
  text "Constant" at 12660.85,7402.44 h60
  text "Board Layer Stack" at 13230.71,7402.44 h60
  text "1" at 9811.59,7282.44 h60
  text "Top Overlay" at 10221.51,7282.44 h60
  text "2" at 9811.59,7162.44 h60
  text "Top Solder" at 10221.51,7162.44 h60
  text "Solder Resist" at 11151.25,7162.44 h60
  text "0.40mil" at 12011.02,7162.44 h60
  text "3.5" at 12660.85,7162.44 h60
  text "3" at 9811.59,7042.44 h60
  text "Top Layer" at 10221.51,7042.44 h60
  text "Copper" at 11151.25,7042.44 h60
  text "1.40mil" at 12011.02,7042.44 h60
  text "4" at 9811.59,6922.44 h60
  text "Dielectric1" at 10221.51,6922.44 h60
  text "FR-4" at 11151.25,6922.44 h60
  text "59.20mil" at 12011.02,6922.44 h60
  text "4.8" at 12660.85,6922.44 h60
  text "5" at 9811.59,6802.44 h60
  text "Bottom Layer" at 10221.51,6802.44 h60
  text "Copper" at 11151.25,6802.44 h60
  text "1.40mil" at 12011.02,6802.44 h60
  text "6" at 9811.59,6682.44 h60
  text "Bottom Solder" at 10221.51,6682.44 h60
  text "Solder Resist" at 11151.25,6682.44 h60
  text "0.40mil" at 12011.02,6682.44 h60
  text "3.5" at 12660.85,6682.44 h60
  text "7" at 9811.59,6562.44 h60
  text "Bottom Overlay" at 10221.51,6562.44 h60
  text ".Layer_Name" at 577,-858.49 h60
M13 Component Bodies Top:
  text ".Layer_Name" at 577,-858.49 h60
M14 Component Bodies Bottom:
  text ".Layer_Name" at 577,-858.49 h60
M15 Courtyards Top:
  text ".Layer_Name" at 577,-858.49 h60
M16 Courtyards Bottom:
  text ".Layer_Name" at 577,-858.49 h60
Drill Drawing:
  circle w10: c5348.72,3067.95 r22.07
  lines w10: 5326.65,2990.7 5370.79,2990.7 5348.72,2946.56 5326.65,2990.7 ; 5326.65,3145.2 5370.79,3145.2 5370.79,3189.34 5326.65,3189.34 5326.65,3145.2 ; 5326.65,3244.52 5348.72,3255.55 5370.79,3244.52 5359.75,3266.59 5370.79,3288.66 5348.72,3277.62 5326.65,3288.66 5337.68,3266.59 5326.65,3244.52 ; 5326.65,3343.84 5370.79,3343.84 5370.79,3387.98 5326.65,3387.98 5326.65,3343.84 ; 5326.65,3454.19 5337.68,3454.19 5348.72,3443.16 5359.75,3454.19 5370.79,3454.19 5359.75,3465.23 5370.79,3476.26 5359.75,3476.26 5348.72,3487.3 5337.68,3476.26 5326.65,3476.26 5337.68,3465.23 5326.65,3454.19 ; 5335.47,3352.66 5361.96,3352.66 5361.96,3379.15 5335.47,3379.15 5335.47,3352.66
  lines w12: 5286,2916.76 8397.21,2916.76 ; 5286,3512.68 8397.21,3512.68 ; 5601.49,2817.44 5601.49,3612 ; 5918.58,2817.44 5918.58,3612 ; 6540.22,2817.44 6540.22,3612 ; 6784.41,2817.44 6784.41,3612 ; 7144.66,2817.44 7144.66,3612 ; 7853.12,2817.44 7853.12,3612 ; 5286,2817.44 8397.21,2817.44 8397.21,3612 5286,3612 5286,2817.44
  text "Symbol" at 5345.59,3542.48 h72
  text "Quantity" at 5631.28,3542.48 h72
  text "Finished Hole Size" at 5948.38,3542.48 h72
  text "Plated" at 6570.02,3542.48 h72
  text "Hole Type" at 6814.21,3542.48 h72
  text "Drill Layer Pair" at 7174.45,3542.48 h72
  text "Hole Tolerance" at 7882.92,3542.48 h72
  text "74" at 5631.28,3443.16 h60
  text "7.87mil (0.200mm)" at 5948.38,3443.16 h60
  text "PTH" at 6570.02,3443.16 h60
  text "Round" at 6814.21,3443.16 h60
  text "Top Layer - Bottom Layer" at 7174.45,3443.16 h60
  text "270" at 5631.28,3343.84 h60
  text "10.00mil (0.254mm)" at 5948.38,3343.84 h60
  text "PTH" at 6570.02,3343.84 h60
  text "Round" at 6814.21,3343.84 h60
  text "Top Layer - Bottom Layer" at 7174.45,3343.84 h60
  text "1" at 5631.28,3244.52 h60
  text "12.00mil (0.305mm)" at 5948.38,3244.52 h60
  text "PTH" at 6570.02,3244.52 h60
  text "Round" at 6814.21,3244.52 h60
  text "Top Layer - Bottom Layer" at 7174.45,3244.52 h60
  text "16" at 5631.28,3145.2 h60
  text "40.00mil (1.016mm)" at 5948.38,3145.2 h60
  text "PTH" at 6570.02,3145.2 h60
  text "Round" at 6814.21,3145.2 h60
  text "Top Layer - Bottom Layer" at 7174.45,3145.2 h60
  text "40" at 5631.28,3045.88 h60
  text "40.16mil (1.020mm)" at 5948.38,3045.88 h60
  text "PTH" at 6570.02,3045.88 h60
  text "Round" at 6814.21,3045.88 h60
  text "Top Layer - Bottom Layer" at 7174.45,3045.88 h60
  text "6" at 5631.28,2946.56 h60
  text "47.24mil (1.200mm)" at 5948.38,2946.56 h60
  text "PTH" at 6570.02,2946.56 h60
  text "Round" at 6814.21,2946.56 h60
  text "Top Layer - Bottom Layer" at 7174.45,2946.56 h60
  text "407 Total" at 5631.28,2847.24 h60
  text ".Layer_Name" at 577,-858.49 h60
M17 Embedded Cavity:
  text ".Layer_Name" at 577,-858.49 h60
M18 Embedded Assembly:
  text ".Layer_Name" at 577,-858.49 h60
M19 Embedded Keepout:
  text ".Layer_Name" at 577,-858.49 h60

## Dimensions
2559.06,687 to 4950.79,688.98 on M2 Board Dimensions
2559.06,687 to 2559.06,3051.18 on M2 Board Dimensions
0,-400 to 1000,-400 on M2 Board Dimensions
